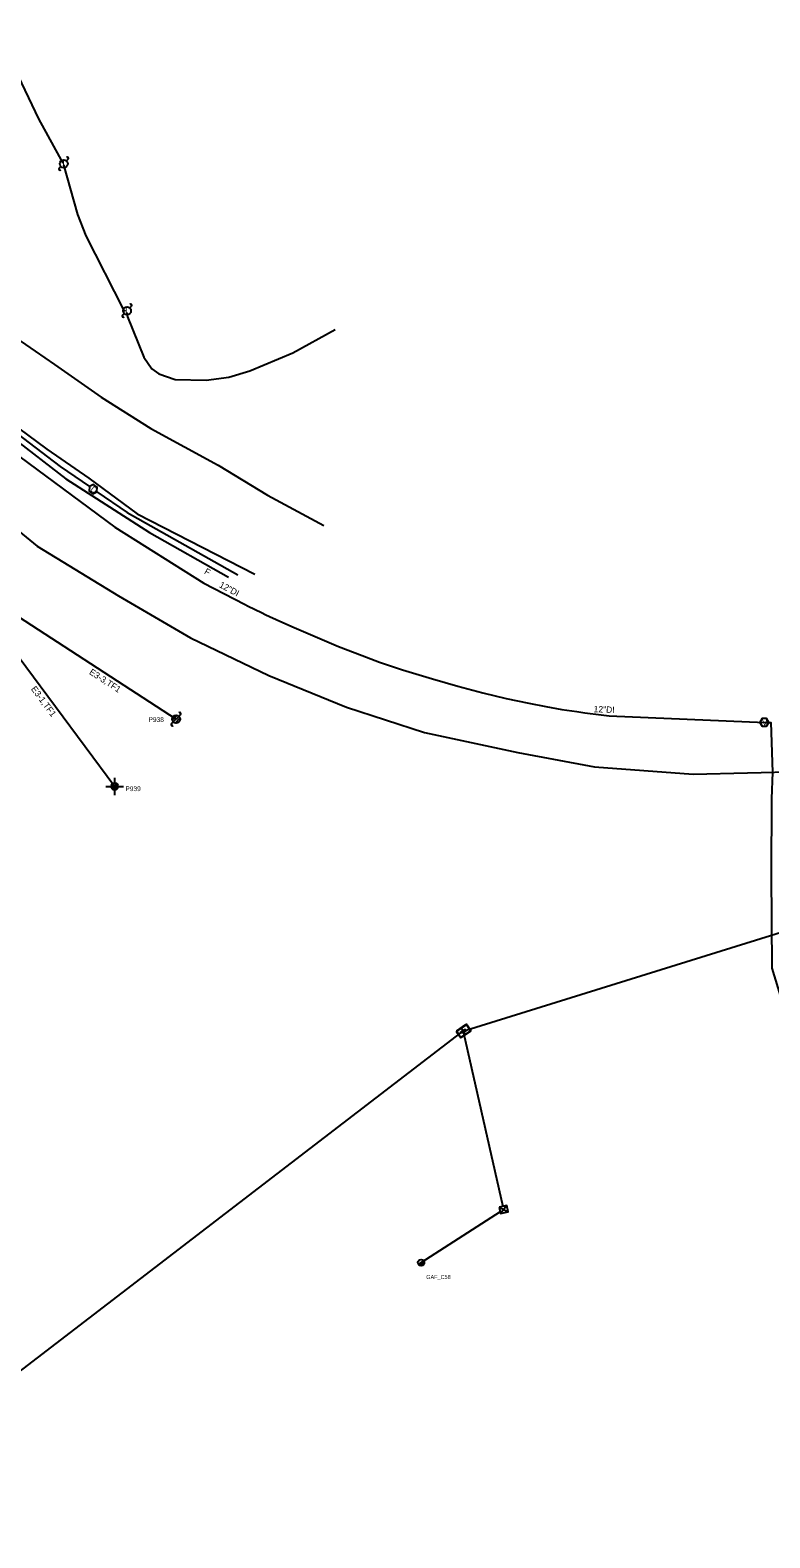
# Model space of a CAD drawing. Extents: x 1614474 to 1865144, y 1098877 to 1212550.
# Drawn here: x 1788482 to 1788947, y 1182960 to 1183909 of the extents above; entities that cross this region are included whole.
import ezdxf

# ---------------------------------------------------------------- set-up
doc = ezdxf.new("R2010")
doc.units = 0
for name, color, linetype in [('BFUSER_CABINET', 7, 'Continuous'), ('BFUSER_DUCTENCLOSURE', 7, 'Continuous'), ('BFUSER_FIBERNODE', 7, 'Continuous'), ('BFUSER_FIBERNODENAME', 7, 'Continuous'), ('BFUSER_FIBERSPAN', 7, 'Continuous'), ('BFUSER_FIBERSPLICEENCLOSURE', 7, 'Continuous'), ('RD_EX_SU_Elec', 7, 'Continuous'), ('RD_EX_SU_Gas', 7, 'Continuous'), ('RD_EX_SU_H2O', 7, 'Continuous'), ('RD_EX_SU_Ovhd', 7, 'Continuous'), ('RD_EX_SU_Pole', 7, 'Continuous'), ('RD_EX_SU_Telecom', 7, 'Continuous'), ('RD_EX_SU_TX_H2O', 7, 'Continuous'), ('RD_EX_SU_TX_Pole', 7, 'Continuous'), ('RD_EX_SU_TX_Telecom', 7, 'Continuous')]:
    doc.layers.add(name, color=color, linetype=linetype)

# ---------------------------------------------------------------- blocks, each defined once
blk = doc.blocks.new('SUE_WV')
at = {"layer": 'RD_EX_SU_H2O'}
blk.add_lwpolyline([(2.89, 0), (1.44, 2.5), (-1.44, 2.5), (-2.89, 0), (-1.44, -2.5), (1.44, -2.5)], close=True, dxfattribs=at)
blk.add_text('V', height=3.75, dxfattribs=at).set_placement((-1.43, -1.88))

msp = doc.modelspace()

# ---------------------------------------------------------------- linework, layer by layer
at = {"layer": 'BFUSER_CABINET'}
for p, q in [((1788777.15, 1183167.69), (1788782.89, 1183164.84)), ((1788782.04, 1183168.75), (1788778, 1183163.78))]:
    msp.add_line(p, q, dxfattribs=at)
msp.add_lwpolyline([(1788777.15, 1183167.69), (1788778, 1183163.78), (1788782.89, 1183164.84), (1788782.04, 1183168.75)], close=True, dxfattribs=at)
at = {"layer": 'BFUSER_DUCTENCLOSURE'}
msp.add_line((1788753.54, 1183280.51), (1788756.07, 1183276.78), dxfattribs=at)
for points in [[(1788752.62, 1183274.74), (1788750.38, 1183278.05)], [(1788750.51, 1183278.75), (1788756.3, 1183282.68)], [(1788752.73, 1183275), (1788750.65, 1183278.06)], [(1788750.76, 1183278.62), (1788756.33, 1183282.4)], [(1788753.29, 1183274.89), (1788758.86, 1183278.67)], [(1788759.11, 1183278.55), (1788753.32, 1183274.61)], [(1788756.88, 1183282.3), (1788758.96, 1183279.23)], [(1788756.99, 1183282.55), (1788759.24, 1183279.24)]]:
    msp.add_lwpolyline(points, dxfattribs=at)
for centre, radius, start, end in [((1788750.79, 1183278.33), 0.5, 124.18741, 214.18741), ((1788750.98, 1183278.29), 0.4, 124.18741, 214.18741), ((1788756.58, 1183282.27), 0.5, 34.18741, 124.18741), ((1788756.55, 1183282.07), 0.4, 34.18741, 124.18741), ((1788758.63, 1183279), 0.4, 304.18741, 34.18741), ((1788758.83, 1183278.96), 0.5, 304.18741, 34.18741), ((1788753.04, 1183275.03), 0.5, 214.18741, 304.18741), ((1788753.06, 1183275.22), 0.4, 214.18741, 304.18741)]:
    msp.add_arc(centre, radius, start, end, dxfattribs=at)
at = {"layer": 'BFUSER_FIBERNODE'}
msp.add_line((1788726.3, 1183131.92), (1788729.83, 1183133.8), dxfattribs=at)
msp.add_lwpolyline([(1788727.36, 1183132.48), (1788728.82, 1183133.26), (1788729.15, 1183132.63), (1788727.7, 1183131.85)], close=True, dxfattribs=at)
msp.add_circle((1788728.07, 1183132.86), 2, dxfattribs=at)
msp.add_arc((1788728.17, 1183132.73), 0.992, 241.80698, 354.09693, dxfattribs=at)
at = {"layer": 'BFUSER_FIBERSPAN'}
for p, q in [((1788754.75, 1183277.57), (1788779.58, 1183168.28)), ((1788777.71, 1183164.78), (1788727.91, 1183132.75))]:
    msp.add_line(p, q, dxfattribs=at)
for points in [[(1788756.44, 1183279.25), (1789284.3, 1183443.63), (1789301.01, 1183495.73), (1789553.74, 1183636.42), (1791469.88, 1184896.13), (1792784.72, 1185784.58)], [(1786621.89, 1182204.64), (1787550.48, 1182536.55), (1787942.78, 1182692.25), (1788048.6, 1182752.86), (1788190.7, 1182871.05), (1788264.4, 1182902.37), (1788753.09, 1183277.48)]]:
    msp.add_lwpolyline(points, dxfattribs=at)
at = {"layer": 'BFUSER_FIBERSPLICEENCLOSURE'}
for p, q in [((1788753.07, 1183278.07), (1788753.08, 1183278.08)), ((1788753.13, 1183277.96), (1788753.07, 1183278.07)), ((1788753.08, 1183278.09), (1788753.4, 1183278.26)), ((1788753.15, 1183277.95), (1788753.08, 1183278.09)), ((1788753.08, 1183278.08), (1788753.14, 1183277.96)), ((1788753.14, 1183277.96), (1788753.13, 1183277.96)), ((1788753.47, 1183278.11), (1788753.15, 1183277.95)), ((1788753.17, 1183277.9), (1788753.5, 1183278.06)), ((1788753.25, 1183277.75), (1788753.17, 1183277.9)), ((1788753.17, 1183277.88), (1788753.18, 1183277.88)), ((1788753.22, 1183277.76), (1788753.17, 1183277.88)), ((1788753.18, 1183277.88), (1788753.24, 1183277.77)), ((1788753.24, 1183277.77), (1788753.22, 1183277.76)), ((1788753.57, 1183277.92), (1788753.25, 1183277.75)), ((1788753.26, 1183277.72), (1788753.58, 1183277.88)), ((1788753.46, 1183277.34), (1788753.26, 1183277.72)), ((1788753.26, 1183277.7), (1788753.27, 1183277.71)), ((1788753.44, 1183277.35), (1788753.26, 1183277.7)), ((1788753.27, 1183277.71), (1788753.45, 1183277.35)), ((1788753.84, 1183277.45), (1788753.35, 1183278.42)), ((1788753.36, 1183278.4), (1788753.45, 1183278.45)), ((1788753.83, 1183277.46), (1788753.36, 1183278.4)), ((1788753.38, 1183278.59), (1788753.52, 1183278.66)), ((1788753.98, 1183277.4), (1788753.38, 1183278.59)), ((1788753.45, 1183277.35), (1788753.44, 1183277.35)), ((1788753.45, 1183278.45), (1788753.93, 1183277.51)), ((1788753.46, 1183278.11), (1788753.49, 1183278.06)), ((1788753.78, 1183277.5), (1788753.46, 1183277.34)), ((1788753.52, 1183278.66), (1788754.12, 1183277.47)), ((1788753.56, 1183277.91), (1788753.81, 1183277.5)), ((1788753.57, 1183278.57), (1788755.52, 1183279.55)), ((1788753.6, 1183278.51), (1788755.55, 1183279.48)), ((1788753.93, 1183277.51), (1788753.83, 1183277.46)), ((1788753.91, 1183278.84), (1788753.89, 1183278.83)), ((1788753.89, 1183278.83), (1788753.93, 1183278.75)), ((1788753.95, 1183278.76), (1788753.91, 1183278.84)), ((1788753.93, 1183278.75), (1788753.95, 1183278.76)), ((1788754.12, 1183277.47), (1788753.98, 1183277.4)), ((1788756.32, 1183278.77), (1788754.04, 1183277.63)), ((1788756.35, 1183278.71), (1788754.08, 1183277.57)), ((1788754.19, 1183278.98), (1788754.17, 1183278.97)), ((1788754.17, 1183278.97), (1788754.21, 1183278.89)), ((1788754.23, 1183278.9), (1788754.19, 1183278.98)), ((1788754.21, 1183278.89), (1788754.23, 1183278.9)), ((1788754.92, 1183279.35), (1788754.89, 1183279.33)), ((1788754.89, 1183279.33), (1788754.93, 1183279.25)), ((1788754.96, 1183279.26), (1788754.92, 1183279.35)), ((1788754.93, 1183279.25), (1788754.96, 1183279.26)), ((1788755.2, 1183279.49), (1788755.18, 1183279.48)), ((1788755.18, 1183279.48), (1788755.22, 1183279.4)), ((1788755.24, 1183279.41), (1788755.2, 1183279.49)), ((1788755.22, 1183279.4), (1788755.24, 1183279.41)), ((1788755.55, 1183279.48), (1788755.61, 1183279.37)), ((1788755.61, 1183279.52), (1788755.67, 1183279.4)), ((1788755.76, 1183279.37), (1788755.96, 1183279.47)), ((1788755.79, 1183279.31), (1788755.99, 1183279.41)), ((1788755.99, 1183279.41), (1788756.32, 1183278.77)), ((1788756.06, 1183279.44), (1788756.38, 1183278.8))]:
    msp.add_line(p, q, dxfattribs=at)
for centre, radius, start, end in [((1788753.39, 1183278.28), 0.0265, 296.71124, 27.40152), ((1788753.48, 1183278.09), 0.0265, 26.02096, 116.71124), ((1788753.48, 1183278.09), 0.0265, 296.71124, 27.40152), ((1788753.58, 1183277.89), 0.0265, 26.02096, 116.71124), ((1788753.79, 1183277.48), 0.0265, 26.02096, 116.71124), ((1788755.55, 1183279.48), 0.0694, 26.71124, 116.71124), ((1788755.74, 1183279.17), 0.42, 45.5934, 113.71817), ((1788755.74, 1183279.17), 0.392, 51.75716, 110.66896), ((1788755.73, 1183279.43), 0.139, 206.71124, 296.71124), ((1788755.73, 1183279.43), 0.0694, 206.71124, 296.71124), ((1788755.99, 1183279.41), 0.0694, 26.66289, 116.71124), ((1788755.52, 1183278.77), 0.857, 358.72179, 51.55451), ((1788756.32, 1183278.77), 0.0694, 296.71124, 26.66289)]:
    msp.add_arc(centre, radius, start, end, dxfattribs=at)
at = {"layer": 'RD_EX_SU_Elec'}
for points in [[(1788463.63, 1183915.38), (1788465.57, 1183904.08), (1788472.46, 1183884.24), (1788487.22, 1183853.04), (1788502.67, 1183825.07)], [(1788502.94, 1183824.03), (1788511.78, 1183792.86), (1788517.03, 1183779.34), (1788540.86, 1183732.77), (1788542.1, 1183732.22)], [(1788389.93, 1183769.66), (1788395.14, 1183768.03), (1788435.26, 1183742.29), (1788466.87, 1183719.3), (1788497.37, 1183698.23), (1788526.63, 1183677.69), (1788558.07, 1183658.04), (1788600.25, 1183634.86), (1788631.33, 1183616.13), (1788666.76, 1183597.01)], [(1788293.02, 1183749.36), (1788312.59, 1183754.98), (1788336.16, 1183758.3), (1788346, 1183757.75), (1788357.76, 1183755.59), (1788367.69, 1183750.09), (1788392.99, 1183727.64), (1788415.29, 1183707.27), (1788443.82, 1183682.26), (1788474.75, 1183658.14), (1788492.46, 1183645.08), (1788518.88, 1183626.85), (1788549.3, 1183604.3), (1788623.32, 1183566.38)], [(1788542.73, 1183731.38), (1788543.26, 1183728.4), (1788553.59, 1183702.92), (1788558.61, 1183695.67), (1788563.06, 1183692.35), (1788573.32, 1183688.8), (1788592.71, 1183688.44), (1788607.07, 1183690.42), (1788620.21, 1183694.36), (1788647.26, 1183705.65), (1788674.01, 1183720.32)]]:
    msp.add_lwpolyline(points, dxfattribs=at)
at = {"layer": 'RD_EX_SU_Gas'}
for points in [[(1788583.03, 1183526.31), (1788632.2, 1183502.48), (1788681.19, 1183482.53), (1788730.18, 1183466.58), (1788788.85, 1183454.04), (1788837.27, 1183444.92), (1788899.36, 1183440.36), (1788967.71, 1183442.07), (1789039.48, 1183448.91), (1789119.8, 1183466.01), (1789142.17, 1183473.37), (1789153.65, 1183476.96), (1789191.08, 1183490.16), (1789257.66, 1183517.77), (1789314.43, 1183549.22), (1789423.9, 1183620.08), (1789825.96, 1183890.59), (1790019.06, 1184020.53)], [(1788246.28, 1183668.74), (1788361.36, 1183740.47), (1788500.88, 1183634.18), (1788519.32, 1183621.45)], [(1788068.19, 1183512.19), (1788110.13, 1183527.52), (1788140.63, 1183538.63), (1788188.65, 1183561.84), (1788213.5, 1183573.42), (1788234.32, 1183584.5), (1788254.09, 1183595.57), (1788276.18, 1183606.45), (1788354.4, 1183643.04), (1788370.81, 1183649.44), (1788385.35, 1183652.25), (1788393.47, 1183651.25), (1788407.97, 1183644.43), (1788437.53, 1183623.8), (1788486.35, 1183583.95), (1788537.72, 1183552.63), (1788583.03, 1183526.31)], [(1788524.07, 1183618.17), (1788543.04, 1183605.06), (1788612.67, 1183565.81)]]:
    msp.add_lwpolyline(points, dxfattribs=at)
msp.add_lwpolyline([(1788524.07, 1183618.17), (1788524.3, 1183621.04), (1788521.93, 1183622.68), (1788519.32, 1183621.45), (1788519.09, 1183618.57), (1788521.46, 1183616.93)], close=True, dxfattribs=at)
at = {"layer": 'RD_EX_SU_H2O'}
msp.add_line((1788846.39, 1183477.1), (1788944.51, 1183472.99), dxfattribs=at)
for points in [[(1788303.91, 1183698.73), (1788334.75, 1183706.75), (1788351.35, 1183710.36), (1788370.26, 1183714.14), (1788375.65, 1183712.39), (1788389.34, 1183703.67), (1788423.85, 1183679.1), (1788469.84, 1183644.46), (1788535.28, 1183595.88), (1788591.36, 1183560.72)], [(1788591.36, 1183560.72), (1788616.84, 1183547.44), (1788619.32, 1183546.2), (1788627.69, 1183542.13), (1788630.41, 1183540.81), (1788639.2, 1183536.67), (1788648.07, 1183532.72), (1788657.04, 1183528.93), (1788676.06, 1183520.81), (1788691, 1183515.07), (1788701.82, 1183510.92), (1788716.37, 1183506.06), (1788735.23, 1183500.35), (1788751.2, 1183495.77), (1788766.82, 1183491.64), (1788781.54, 1183488.14), (1788795.76, 1183485.13), (1788806.64, 1183482.95), (1788816.59, 1183481.18), (1788825.97, 1183479.78), (1788831.06, 1183478.99), (1788841.41, 1183477.66), (1788846.39, 1183477.1)], [(1788944.51, 1183472.99), (1788948.08, 1183472.98), (1788949.11, 1183441.6), (1788948.62, 1183424.91), (1788948.38, 1183377.72), (1788948.86, 1183318.31), (1788982.12, 1183209), (1789006.79, 1183167.73), (1789013.53, 1183152.59), (1789041.56, 1183104.35), (1789077.27, 1183039.85), (1789126.08, 1183015.33), (1789145.03, 1183006.76), (1789188.4, 1182981.94)]]:
    msp.add_lwpolyline(points, dxfattribs=at)
at = {"layer": 'RD_EX_SU_Ovhd'}
for p, q in [((1788422.18, 1183585.21), (1788535.23, 1183432.65)), ((1788470.31, 1183542.42), (1788573.83, 1183475.03))]:
    msp.add_line(p, q, dxfattribs=at)
at = {"layer": 'RD_EX_SU_Pole'}
for p, q in [((1788504.94, 1183826.5), (1788506, 1183827.56)), ((1788500.34, 1183821.91), (1788501.4, 1183822.97)), ((1788544.75, 1183733.91), (1788545.81, 1183734.97)), ((1788540.15, 1183729.31), (1788541.21, 1183730.37)), ((1788571.42, 1183474.38), (1788574.48, 1183477.44)), ((1788572.06, 1183473.26), (1788575.6, 1183476.79)), ((1788575.6, 1183476.79), (1788576.66, 1183477.85)), ((1788571, 1183472.2), (1788572.06, 1183473.26)), ((1788573.18, 1183472.61), (1788576.25, 1183475.67)), ((1788535.23, 1183434.87), (1788535.23, 1183438.18)), ((1788529.71, 1183432.65), (1788533.02, 1183432.65)), ((1788533.02, 1183432.79), (1788535.11, 1183434.86)), ((1788533.27, 1183431.62), (1788536.27, 1183434.61)), ((1788533.92, 1183430.86), (1788537.03, 1183433.95)), ((1788534.93, 1183430.45), (1788537.43, 1183432.95)), ((1788535.23, 1183427.12), (1788535.23, 1183430.43)), ((1788537.45, 1183432.65), (1788540.76, 1183432.65))]:
    msp.add_line(p, q, dxfattribs=at)
for centre, radius in [((1788503.17, 1183824.74), 2.5), ((1788542.98, 1183732.14), 2.5), ((1788573.83, 1183475.03), 2.5), ((1788535.23, 1183432.65), 2.22)]:
    msp.add_circle(centre, radius, dxfattribs=at)
for centre, start, end in [((1788505.47, 1183828.09), 315, 135), ((1788500.87, 1183821.38), 135, 315), ((1788545.28, 1183735.5), 315, 135), ((1788540.68, 1183728.78), 135, 315), ((1788576.13, 1183478.38), 315, 135), ((1788571.53, 1183471.67), 135, 315)]:
    msp.add_arc(centre, 0.75, start, end, dxfattribs=at)
at = {"layer": 'RD_EX_SU_Telecom'}
msp.add_lwpolyline([(1788051.48, 1183573.81), (1788075.38, 1183583.55), (1788095.79, 1183593.05), (1788114.26, 1183599.21), (1788134.29, 1183610.32), (1788148.6, 1183623.99), (1788177.58, 1183645.02), (1788202.47, 1183672.68), (1788217.16, 1183679.23), (1788236.69, 1183693.23), (1788260.97, 1183706.32), (1788311.94, 1183723.38), (1788317.79, 1183725.03), (1788330.54, 1183724.81), (1788354.61, 1183726.4), (1788370.7, 1183722.47), (1788387.37, 1183715.03), (1788405.99, 1183702.43), (1788436.8, 1183679.42), (1788470.31, 1183652.69), (1788504.56, 1183626.37), (1788557.16, 1183592.46), (1788606.87, 1183564.42)], dxfattribs=at)

# ---------------------------------------------------------------- block references
at = {"layer": 'RD_EX_SU_H2O'}
msp.add_blockref('SUE_WV', (1788944.03, 1183473.03), dxfattribs=at)

# ---------------------------------------------------------------- texts
at = {"layer": 'BFUSER_FIBERNODENAME'}
msp.add_text('GAF_C58', height=2.5, rotation=0.00021, dxfattribs=at).set_placement((1788731.29, 1183122.54))
at = {"layer": 'RD_EX_SU_Gas'}
msp.add_text('D', height=3.75, rotation=325.36878, dxfattribs=at).set_placement((1788519.6, 1183618.98))
at = {"layer": 'RD_EX_SU_Ovhd'}
for s, rotation, p in [('E3-3,TF1', 326.93629, (1788518.81, 1183503.69)), ('E3-1,TF1', 306.54056, (1788482.32, 1183493.97))]:
    msp.add_text(s, height=4, rotation=rotation, dxfattribs=at).set_placement(p)
at = {"layer": 'RD_EX_SU_Pole'}
for p in [(1788502.31, 1183822.74), (1788542.12, 1183730.14)]:
    msp.add_text('L', height=4, dxfattribs=at).set_placement(p)
at = {"layer": 'RD_EX_SU_TX_H2O'}
for rotation, p in [(332.01699, (1788600.59, 1183558.34)), (357.37893, (1788836.54, 1183479.45))]:
    msp.add_text('12"DI', height=4, rotation=rotation, dxfattribs=at).set_placement(p)
at = {"layer": 'RD_EX_SU_TX_Pole'}
for s, p in [('P938', (1788556.5, 1183473.26)), ('P939', (1788541.98, 1183429.72))]:
    msp.add_text(s, height=3, dxfattribs=at).set_placement(p)
at = {"layer": 'RD_EX_SU_TX_Telecom'}
msp.add_text('F', height=4, rotation=330.58126, dxfattribs=at).set_placement((1788591.19, 1183566.83))

doc.saveas('drawing.dxf')
